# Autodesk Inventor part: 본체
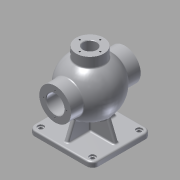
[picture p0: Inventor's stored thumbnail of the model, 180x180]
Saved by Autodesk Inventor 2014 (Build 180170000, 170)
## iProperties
Created: 2015-10
Part Number: 본체
Material: Aluminum 6061
Document SubType Name: Modeling
Designer: youjin21
Density: 2.71 g/cm^3
Appearance: Aluminum - Flat
Mass: 1509.57 g
Surface Area: 1153.7 cm^2
Volume: 557.037 cm^3
Author: youjin21
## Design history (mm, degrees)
sketch "Sketch1"
  geometry: L1 (-50.5, -57.5)-(50.5, -57.5); L2 (62.5, -45.5)-(62.5, 45.5); L3 (50.5, 57.5)-(-50.5, 57.5); L4 (-62.5, 45.5)-(-62.5, -45.5); L5 (-62.5, -57.5)-(62.5, 57.5); L6 (62.5, -57.5)-(-62.5, 57.5); A1 r 12 centre (-50.5, 45.5) between (-50.5, 57.5) and (-62.5, 45.5); A2 r 12 centre (-50.5, -45.5) between (-62.5, -45.5) and (-50.5, -57.5); A3 r 12 centre (50.5, -45.5) between (50.5, -57.5) and (62.5, -45.5); A4 r 12 centre (50.5, 45.5) between (62.5, 45.5) and (50.5, 57.5); 1 further point
  constraints: 12 end point, 8 point on circle, 8 point on line, 8 tangent, 4 centre point, 3 equal radius, 2 midpoint, 2 parallel, 1 horizontal, 1 perpendicular
  dimensions: "d0" = 125 distance of L6.end L5.end; "d1" = 115 distance of L5.end L6.start; "d2" = 12 radius of A1
extrude "Extrusion1" new body sketch "Sketch1" distance "d3" = 10; taper "d4" = 0 deg
sketch "Sketch2"
  geometry: A1 r 12 centre (-50.5, -45.5) between (-62.5, -45.5) and (-50.5, -57.5) reference; A2 r 12 centre (50.5, -45.5) between (50.5, -57.5) and (62.5, -45.5) reference; A3 r 12 centre (50.5, 45.5) between (62.5, 45.5) and (50.5, 57.5) reference; A4 r 12 centre (-50.5, 45.5) between (-50.5, 57.5) and (-62.5, 45.5) reference; 5 further points
  constraints: 4 coincident
hole "Hole1" sketch "Sketch2" at (-50.5, 45.5), (50.5, 45.5), (50.5, -45.5), (-50.5, -45.5) diameter "d5" = 8; stored, may be unused: countersink angle "d9" = 90 deg, drill point angle "d11" = 0 deg; dims "d6" = 6, "d7" = 12, "d8" = 3, "d10" = 8
sketch "Sketch3"
  geometry: L1 (0, 32)-(0, 138); A1 r 53 centre (0, 85) between (0, 32) and (0, 138); 2 further points
  constraints: 2 end point, 2 point on circle, 1 centre point, 1 coincident, 1 midpoint, 1 vertical, 1 vertical alignment
  dimensions: "d12" = 106 diameter of A1; "d13" = 85 distance of point (0, 0) A1.centre
revolve "Revolution1" sketch "Sketch3" stored, may be unused: angle "d14" = 90 deg
sketch "Sketch4"
  geometry: L1 (-4, -4)-(4, -4); L2 (4, -4)-(4, 4); L3 (4, 4)-(-4, 4); L4 (-4, 4)-(-4, -4); L5 (-4, -4)-(4, 4); L6 (4, -4)-(-4, 4); 1 further point
  constraints: 12 end point, 2 midpoint, 2 parallel, 1 horizontal, 1 perpendicular
  dimensions: "d15" = 8 distance of L3.end L2.end; "d16" = 8 distance of L2.end L1.end
extrude "Extrusion2" join sketch "Sketch4" stored distance "d17" = 10; taper "d18" = 0 deg
workplane "Work Plane1"
sketch "Sketch7"
  geometry: L1 (-50.5, 0)-(50.5, 0) reference; C1 r 31 at (0, 85); 1 further point
  constraints: 1 centre point, 1 vertical alignment
  dimensions: "d20" = 62 diameter of C1; "d21" = 85 distance from line of L1 C1.centre
extrude "Extrusion3" join sketch "Sketch7" stored distance "d22" = 10; taper "d23" = 0 deg
sketch "Sketch8"
  geometry: C1 r 31 at (0, 0) reference; C2 r 17.5 at (0, 0); 1 further point
  constraints: 1 centre point, 1 coincident
  dimensions: "d26" = 35 diameter of C2
sketch "Sketch9"
  geometry: L1 (0, 128)-(0, 42); A1 r 53 centre (0, 85) between (4, 32.151) and (-4, 32.151) reference; A2 r 43 centre (0, 85) between (0, 42) and (0, 128); 2 further points
  constraints: 2 coincident, 2 end point, 2 point on circle, 1 centre point, 1 midpoint, 1 vertical
  dimensions: "d24" = 86 diameter of A2
revolve "Revolution2" sketch "Sketch9" stored, may be unused: angle "d25" = 90 deg
extrude "Extrusion4" cut sketch "Sketch8" stored distance "d27" = 10; taper "d28" = 0 deg
mirror "Mirror1"
workplane "Work Plane2"
sketch "Sketch11"
  geometry: C1 r 27 at (0, 0); 1 further point
  constraints: 1 centre point, 1 coincident
  dimensions: "d30" = 54 diameter of C1
extrude "Extrusion5" join sketch "Sketch11" stored distance "d31" = 10; taper "d32" = 0 deg
sketch "Sketch12"
  geometry: C1 r 27 at (0, 0) reference; C2 r 13 at (0, 0)
  constraints: 1 centre point, 1 coincident
  dimensions: "d33" = 26 diameter of C2
extrude "Extrusion6" cut sketch "Sketch12" stored distance "d34" = 10; taper "d35" = 0 deg
sketch "Sketch13"
  geometry: C1 r 13 at (0, 0) reference; C2 r 27 at (0, 0) reference; A1 r 20 centre (0, 0) between (0, 20) and (-20, 0); 2 further points
  constraints: 4 point on circle, 2 horizontal alignment, 2 vertical alignment, 1 centre point, 1 coincident
  dimensions: "d36" = 40 diameter of A1
hole "Hole2" sketch "Sketch13" at (0, 20), (-20, 0), (0, -20), (20, 0) diameter "d37" = 3.242; stored, may be unused: countersink angle "d41" = 90 deg, drill point angle "d43" = 118 deg; dims "d38" = 9, "d39" = 12, "d40" = 3, "d42" = 11
sketch "Sketch14"
  geometry: C1 r 17.5 at (0, 0) reference; C2 r 31 at (0, 0) reference; A1 r 22.5 centre (0, 0) between (0, 22.5) and (-22.5, 0); 3 further points
  constraints: 4 point on circle, 2 horizontal alignment, 2 vertical alignment, 1 centre point, 1 coincident
  dimensions: "d44" = 45 diameter of A1
hole "Hole3" sketch "Sketch14" at (0, 22.5), (-22.5, 0), (22.5, 0), (0, -22.5) diameter "d45" = 3.242; stored, may be unused: countersink angle "d49" = 90 deg, drill point angle "d51" = 118 deg; dims "d46" = 12, "d47" = 4, "d48" = 2, "d50" = 15
sketch "Sketch16"
  geometry: C1 r 17.5 at (0, 0) reference; C2 r 31 at (0, 0) reference; A1 r 24 centre (0, 0) between (0, 24) and (-24, 0); 3 further points
  constraints: 4 point on circle, 2 horizontal alignment, 2 vertical alignment, 1 centre point, 1 coincident
  dimensions: "d52" = 48 diameter of A1
hole "Hole4" sketch "Sketch16" at (0, 24), (-24, 0), (0, -24), (24, 0) diameter "d53" = 3.242; stored, may be unused: countersink angle "d57" = 90 deg, drill point angle "d59" = 118 deg; dims "d54" = 16, "d55" = 4, "d56" = 2, "d58" = 19
workplane "Work Plane3"
sketch "Sketch17"
  geometry: C1 r 17.5 at (0, 85) reference; C2 r 18.5 at (0, 85); 1 further point
  constraints: 1 centre point, 1 coincident
  dimensions: "d61" = 37 diameter of C2
extrude "Extrusion7" cut sketch "Sketch17" distance "d62" = 1.75; taper "d63" = 0 deg
sketch "Sketch19"
  geometry: L1 (62.5, 10)-(50.5, 10) reference; L2 (-50.5, 10)-(50.5, 10) reference; L3 (-50.5, 10)-(-62.5, 10) reference; L4 (37.379, 47.426)-(52.5, 10); L5 (-37.379, 47.426)-(-52.5, 10); L6 (62.5, 0)-(62.5, 10) reference; L7 (-62.5, 0)-(-62.5, 10) reference; A1 r 53 centre (0, 85) between (-27, 130.607) and (27, 130.607) reference; 1 further point
  constraints: 4 end point, 2 point on circle, 2 point on line
  dimensions: "d64" = 10 distance of L4.end L1.start; "d65" = 10 distance of L3.end L5.end; "d66" = 22 deg angle of L4 L6; "d67" = 22 deg angle of L7 L5
feature "Rib1" dims "d68" = 1, "d69" = 8, "d70" = 0, "d71" = 0, "d72" = 1, "d73" = 1
feature "Rib2" dims "d74" = 1, "d75" = 8, "d76" = 0, "d77" = 0, "d78" = 1, "d79" = 1
sketch "Sketch21"
  geometry: L1 (45.5, 10)-(-45.5, 10) reference; L2 (39.5, 10)-(51.5, 10) reference; L3 (57.5, 10)-(45.5, 10) reference; L4 (-45.5, 10)-(-57.5, 10) reference; L5 (33.719, 44.109)-(47.5, 10); L6 (-33.719, 44.109)-(-47.5, 10); L7 (57.5, 0)-(57.5, 10) reference; L8 (-57.5, 0)-(-57.5, 10) reference; A1 r 53 centre (0, 85) between (42.988, 116) and (42.988, 54) reference; 1 further point
  constraints: 4 end point, 2 point on circle, 2 point on line
  dimensions: "d80" = 10 distance of L6.end L4.end; "d81" = 10 distance of L3.start L5.end; "d82" = 22 deg angle of L7 L5; "d83" = 22 deg angle of L6 L8
feature "Rib3" dims "d84" = 1, "d85" = 8, "d86" = 0, "d87" = 0, "d88" = 1, "d89" = 1
feature "Rib4" dims "d90" = 1, "d91" = 8, "d92" = 0, "d93" = 0, "d94" = 1, "d95" = 1
fillet "Fillet1" dims "d96" = 3
fillet "Fillet2" dims "d97" = 3
fillet "Fillet3" dims "d98" = 3
fillet "Fillet4" dims "d99" = 3
chamfer "Chamfer1" distance "d100" = 1; stored, may be unused: second distance "d101" = 2, angle "d102" = 45 deg
workplane "Work Plane12"
sketch "Sketch32"
  geometry: L1 (-27, 150)-(27, 150) reference; 3 further points
  constraints: 1 midpoint, 1 vertical alignment, 1 other
  dimensions: "d122" = 10 distance from line of point (0, 140) L1
emboss "Emboss4" sketch "Sketch32" dims "d123" = 0.5, "d124" = 0
body "Solid1"
other parameters: "d19" = -68, "d60" = 52, "d121" = -26.5
